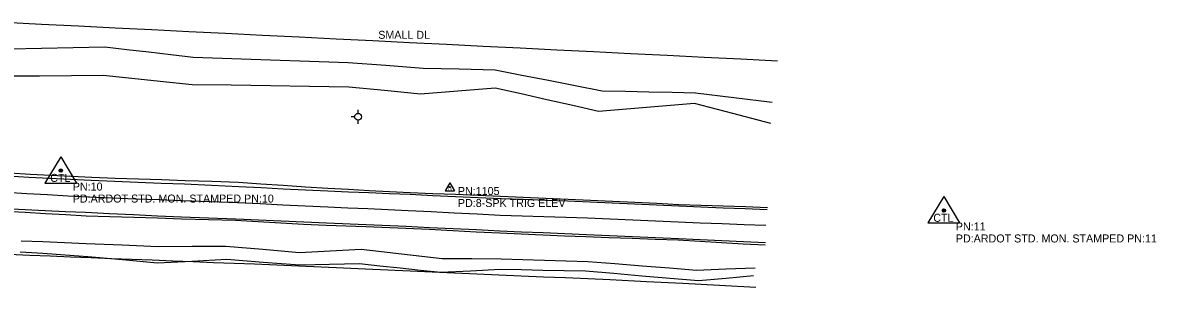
# Model space of a CAD drawing. Extents: x 1138803 to 1169983, y 1655906 to 1658226.
# Drawn here: x 1149908 to 1150616, y 1657386 to 1657552 of the extents above; entities that cross this region are included whole.
import ezdxf

# ---------------------------------------------------------------- set-up
doc = ezdxf.new("R2010")
doc.units = 0
for name, color, linetype in [('S_DITCHLINE', 7, 'Continuous'), ('S_EDGE_PAVEMENT', 7, 'Continuous'), ('S_MSC_PT_SYM', 7, 'Continuous'), ('S_PAVEMENT_CROWN', 7, 'Continuous'), ('S_PRIMARY_CTL', 7, 'Continuous'), ('S_PRIMARY_CTL_ANNOT', 7, 'Continuous'), ('S_SECONDARY_CTL', 7, 'Continuous'), ('S_SECONDARY_CTL_ANNOT', 7, 'Continuous'), ('S_SHOULDER', 7, 'Continuous'), ('S_SURVEY_TEXT_ANNOT', 7, 'Continuous'), ('S_TREE', 7, 'Continuous'), ('S_UTILITY_POLE', 7, 'Continuous')]:
    doc.layers.add(name, color=color, linetype=linetype)

msp = doc.modelspace()

# ---------------------------------------------------------------- linework, layer by layer
at = {"layer": 'S_DITCHLINE'}
for points in [[(1150375.87, 1657501.82), (1150351.88, 1657504.76), (1150327.89, 1657507.69), (1150313.29, 1657508), (1150298.7, 1657508.3), (1150284.1, 1657508.61), (1150269.51, 1657508.91), (1150252.82, 1657512.19), (1150236.14, 1657515.47), (1150219.45, 1657518.75), (1150202.76, 1657522.04), (1150180.28, 1657522.57), (1150157.8, 1657523.11), (1150134.34, 1657524.9), (1150110.88, 1657526.7), (1150086.66, 1657527.53), (1150062.44, 1657528.36), (1150038.22, 1657529.19), (1150014.01, 1657530.02), (1150000.22, 1657531.62), (1149986.44, 1657533.23), (1149972.66, 1657534.83), (1149958.88, 1657536.43), (1149939.08, 1657536.02), (1149919.29, 1657535.62), (1149899.49, 1657535.21)], [(1150374.96, 1657488.71), (1150351.16, 1657494.98), (1150327.36, 1657501.26), (1150312.35, 1657499.99), (1150297.35, 1657498.72), (1150282.34, 1657497.45), (1150267.34, 1657496.18), (1150251.21, 1657499.84), (1150235.08, 1657503.51), (1150218.95, 1657507.18), (1150202.83, 1657510.85), (1150179.42, 1657508.91), (1150156, 1657506.97), (1150133.64, 1657509.21), (1150111.27, 1657511.44), (1150086.79, 1657511.82), (1150062.31, 1657512.2), (1150037.83, 1657512.58), (1150013.35, 1657512.95), (1149999.47, 1657514.36), (1149985.6, 1657515.78), (1149971.72, 1657517.19), (1149957.85, 1657518.6), (1149937.99, 1657518.48), (1149918.12, 1657518.35), (1149898.26, 1657518.23)], [(1150365.15, 1657398.18), (1150346.88, 1657397.42), (1150328.61, 1657396.66), (1150311.6, 1657398.03), (1150294.58, 1657399.39), (1150277.57, 1657400.76), (1150260.55, 1657402.12), (1150247.03, 1657402.53), (1150233.51, 1657402.94), (1150219.99, 1657403.34), (1150206.47, 1657403.75), (1150188.08, 1657403.84), (1150169.7, 1657403.92), (1150157.01, 1657405.37), (1150144.32, 1657406.81), (1150131.63, 1657408.25), (1150118.94, 1657409.69), (1150099.7, 1657408.71), (1150080.46, 1657407.73), (1150057.51, 1657409.72), (1150034.55, 1657411.7), (1150013.35, 1657411.6), (1149992.14, 1657411.5), (1149969.72, 1657412.46), (1149947.31, 1657413.42), (1149933.77, 1657413.98), (1149920.24, 1657414.54), (1149906.71, 1657415.09)], [(1150364.23, 1657393.32), (1150346.97, 1657391.72), (1150329.7, 1657390.13), (1150312.09, 1657391.65), (1150294.47, 1657393.17), (1150276.85, 1657394.7), (1150259.23, 1657396.22), (1150245.9, 1657396.46), (1150232.56, 1657396.71), (1150219.22, 1657396.95), (1150205.88, 1657397.19), (1150187.34, 1657396.24), (1150168.79, 1657395.29), (1150156.09, 1657396.67), (1150143.39, 1657398.05), (1150130.68, 1657399.43), (1150117.98, 1657400.81), (1150099.31, 1657400.39), (1150080.63, 1657399.97), (1150057.86, 1657401.69), (1150035.09, 1657403.41), (1150013.34, 1657402.32), (1149991.6, 1657401.23), (1149969.93, 1657403.2), (1149948.27, 1657405.16), (1149934.18, 1657406.17), (1149920.09, 1657407.18), (1149906, 1657408.18)]]:
    msp.add_lwpolyline(points, dxfattribs=at)
at = {"layer": 'S_EDGE_PAVEMENT'}
for points in [[(1150372.61, 1657434.65), (1150358.85, 1657435.18), (1150345.08, 1657435.72), (1150331.32, 1657436.26), (1150317.56, 1657436.8), (1150303.62, 1657437.45), (1150289.69, 1657438.11), (1150275.76, 1657438.76), (1150261.83, 1657439.41), (1150247.97, 1657439.94), (1150234.12, 1657440.46), (1150220.27, 1657440.99), (1150206.42, 1657441.51), (1150192.21, 1657442.16), (1150178, 1657442.81), (1150163.79, 1657443.46), (1150149.58, 1657444.11), (1150136.74, 1657444.64), (1150123.9, 1657445.18), (1150111.06, 1657445.71), (1150098.22, 1657446.25), (1150084.31, 1657446.94), (1150070.39, 1657447.63), (1150056.48, 1657448.32), (1150042.56, 1657449.01), (1150025.58, 1657449.81), (1150008.59, 1657450.61), (1149994.02, 1657451.17), (1149979.45, 1657451.73), (1149964.88, 1657452.29), (1149950.3, 1657452.86), (1149937.35, 1657453.54), (1149924.4, 1657454.22), (1149911.44, 1657454.9), (1149898.49, 1657455.58)], [(1150371.59, 1657413.89), (1150357.99, 1657414.55), (1150344.39, 1657415.21), (1150330.79, 1657415.87), (1150317.19, 1657416.53), (1150302.85, 1657417.13), (1150288.51, 1657417.74), (1150274.17, 1657418.34), (1150259.83, 1657418.95), (1150246.3, 1657419.54), (1150232.76, 1657420.13), (1150219.22, 1657420.72), (1150205.69, 1657421.31), (1150191.05, 1657422.01), (1150176.42, 1657422.7), (1150161.78, 1657423.4), (1150147.15, 1657424.09), (1150122.21, 1657425.14), (1150097.27, 1657426.19), (1150083.15, 1657426.84), (1150069.03, 1657427.49), (1150054.91, 1657428.15), (1150040.79, 1657428.8), (1150023.75, 1657429.4), (1150006.71, 1657429.99), (1149991.76, 1657430.7), (1149976.81, 1657431.42), (1149961.86, 1657432.13), (1149946.91, 1657432.84), (1149934.28, 1657433.44), (1149921.65, 1657434.05), (1149909.02, 1657434.65), (1149896.39, 1657435.26)]]:
    msp.add_lwpolyline(points, dxfattribs=at)
at = {"layer": 'S_MSC_PT_SYM'}
msp.add_lwpolyline([(1150129.7, 1657546.66), (1150129.7, 1657546.71), (1150129.7, 1657546.66), (1150129.65, 1657546.66), (1150129.7, 1657546.66), (1150129.7, 1657546.61), (1150129.7, 1657546.66), (1150129.75, 1657546.66)], dxfattribs=at)
at = {"layer": 'S_PAVEMENT_CROWN'}
msp.add_lwpolyline([(1150371.93, 1657424.75), (1150358.22, 1657425.27), (1150344.5, 1657425.78), (1150330.79, 1657426.3), (1150317.08, 1657426.82), (1150302.92, 1657427.47), (1150288.77, 1657428.12), (1150274.61, 1657428.77), (1150260.45, 1657429.42), (1150246.82, 1657429.85), (1150233.19, 1657430.27), (1150219.56, 1657430.7), (1150205.93, 1657431.12), (1150191.55, 1657431.84), (1150177.16, 1657432.56), (1150162.78, 1657433.28), (1150148.4, 1657434), (1150135.84, 1657434.57), (1150123.27, 1657435.13), (1150110.71, 1657435.7), (1150098.15, 1657436.27), (1150084.08, 1657436.94), (1150070, 1657437.61), (1150055.93, 1657438.28), (1150041.86, 1657438.95), (1150024.64, 1657439.61), (1150007.43, 1657440.26), (1149992.74, 1657440.82), (1149978.06, 1657441.37), (1149963.37, 1657441.92), (1149948.68, 1657442.47), (1149935.85, 1657443.2), (1149923.02, 1657443.93), (1149910.19, 1657444.66), (1149897.36, 1657445.39)], dxfattribs=at)
at = {"layer": 'S_PRIMARY_CTL'}
for p, q in [((1149931.37, 1657467.86), (1149921.34, 1657451.35)), ((1149931.37, 1657467.86), (1149941.19, 1657451.35)), ((1149921.34, 1657451.35), (1149941.19, 1657451.35)), ((1150483.05, 1657442.88), (1150473.02, 1657426.37)), ((1150483.05, 1657442.88), (1150492.88, 1657426.37)), ((1150473.02, 1657426.37), (1150492.88, 1657426.37))]:
    msp.add_line(p, q, dxfattribs=at)
for centre, radius in [((1149931.37, 1657459.16), 1.04), ((1149931.37, 1657459.16), 0.609), ((1149931.37, 1657459.16), 0.344), ((1150483.05, 1657434.18), 1.04), ((1150483.05, 1657434.18), 0.609), ((1150483.05, 1657434.18), 0.344)]:
    msp.add_circle(centre, radius, dxfattribs=at)
at = {"layer": 'S_SECONDARY_CTL'}
for p, q in [((1150174.47, 1657451.5), (1150171.46, 1657446.55)), ((1150174.47, 1657451.5), (1150177.42, 1657446.55)), ((1150171.46, 1657446.55), (1150177.42, 1657446.55))]:
    msp.add_line(p, q, dxfattribs=at)
for radius in [0.311, 0.183, 0.103]:
    msp.add_circle((1150174.47, 1657448.89), radius, dxfattribs=at)
at = {"layer": 'S_SHOULDER'}
for points in [[(1150372.89, 1657435.91), (1150359.06, 1657436.39), (1150345.22, 1657436.87), (1150331.38, 1657437.34), (1150317.55, 1657437.82), (1150303.73, 1657438.47), (1150289.92, 1657439.13), (1150276.11, 1657439.78), (1150262.29, 1657440.44), (1150248.26, 1657441.09), (1150234.23, 1657441.74), (1150220.19, 1657442.4), (1150206.16, 1657443.05), (1150192.03, 1657443.61), (1150177.9, 1657444.16), (1150163.77, 1657444.72), (1150149.64, 1657445.28), (1150136.79, 1657445.93), (1150123.94, 1657446.59), (1150111.09, 1657447.25), (1150098.24, 1657447.91), (1150084.3, 1657448.85), (1150070.35, 1657449.78), (1150056.41, 1657450.72), (1150042.47, 1657451.66), (1150025.77, 1657452.25), (1150009.07, 1657452.85), (1149994.49, 1657453.32), (1149979.91, 1657453.8), (1149965.33, 1657454.27), (1149950.75, 1657454.75), (1149937.93, 1657455.43), (1149925.11, 1657456.12), (1149912.29, 1657456.81), (1149899.47, 1657457.49)], [(1150371.33, 1657412.38), (1150357.77, 1657413.18), (1150344.22, 1657413.99), (1150330.66, 1657414.79), (1150317.1, 1657415.6), (1150302.69, 1657416.11), (1150288.27, 1657416.62), (1150273.85, 1657417.13), (1150259.43, 1657417.64), (1150245.99, 1657418.21), (1150232.54, 1657418.79), (1150219.09, 1657419.36), (1150205.65, 1657419.93), (1150190.95, 1657420.71), (1150176.26, 1657421.48), (1150161.57, 1657422.25), (1150146.87, 1657423.02), (1150122.01, 1657423.87), (1150097.14, 1657424.73), (1150082.98, 1657425.51), (1150068.82, 1657426.3), (1150054.66, 1657427.09), (1150040.5, 1657427.88), (1150023.61, 1657428.36), (1150006.73, 1657428.85), (1149991.83, 1657429.31), (1149976.94, 1657429.76), (1149962.04, 1657430.22), (1149947.14, 1657430.68), (1149934.45, 1657431.4), (1149921.76, 1657432.12), (1149909.07, 1657432.84), (1149896.37, 1657433.56)]]:
    msp.add_lwpolyline(points, dxfattribs=at)
at = {"layer": 'S_TREE'}
for points in [[(1150379.23, 1657527.75), (1150356.23, 1657528.9), (1150333.24, 1657530.04), (1150310.25, 1657531.19), (1150287.25, 1657532.33), (1150264.26, 1657533.48), (1150241.27, 1657534.62), (1150218.27, 1657535.77), (1150195.28, 1657536.91), (1150172.29, 1657538.06), (1150149.29, 1657539.2), (1150126.3, 1657540.35), (1150103.31, 1657541.49), (1150080.31, 1657542.64), (1150057.32, 1657543.78), (1150034.33, 1657544.92), (1150011.33, 1657546.07), (1149988.34, 1657547.21), (1149965.35, 1657548.36), (1149942.35, 1657549.5), (1149919.36, 1657550.65), (1149896.37, 1657551.79)], [(1150365.62, 1657386.06), (1150342.84, 1657387.23), (1150320.07, 1657388.39), (1150297.29, 1657389.56), (1150274.51, 1657390.72), (1150260.63, 1657391.33), (1150246.74, 1657391.94), (1150232.86, 1657392.55), (1150218.97, 1657393.16), (1150205.09, 1657393.77), (1150191.2, 1657394.39), (1150177.32, 1657395), (1150163.43, 1657395.61), (1150149.55, 1657396.22), (1150135.66, 1657396.83), (1150121.78, 1657397.44), (1150107.89, 1657398.05), (1150094.01, 1657398.66), (1150080.12, 1657399.27), (1150066.24, 1657399.88), (1150052.35, 1657400.49), (1150039.59, 1657401), (1150026.83, 1657401.5), (1150014.06, 1657402), (1150001.3, 1657402.51), (1149988.54, 1657403.01), (1149975.78, 1657403.52), (1149963.02, 1657404.02), (1149950.25, 1657404.52), (1149937.49, 1657405.03), (1149924.73, 1657405.53), (1149911.97, 1657406.04), (1149899.21, 1657406.54)]]:
    msp.add_lwpolyline(points, dxfattribs=at)
at = {"layer": 'S_UTILITY_POLE'}
for p, q in [((1150117.1, 1657494.98), (1150117.1, 1657497.22)), ((1150115, 1657492.84), (1150112.68, 1657492.84)), ((1150117.17, 1657488.43), (1150117.17, 1657490.75))]:
    msp.add_line(p, q, dxfattribs=at)
msp.add_circle((1150117.1, 1657492.87), 2.13, dxfattribs=at)

# ---------------------------------------------------------------- texts
at = {"layer": 'S_PRIMARY_CTL'}
for p in [(1149924.78, 1657452.09), (1150476.47, 1657427.1)]:
    msp.add_text('CTL', height=5, rotation=360, dxfattribs=at).set_placement(p)
at = {"layer": 'S_PRIMARY_CTL_ANNOT'}
for s, p in [('PN:10', (1149938.87, 1657446.66)), ('PD:ARDOT STD. MON. STAMPED PN:10', (1149938.87, 1657439.16)), ('PN:11', (1150490.55, 1657421.68)), ('PD:ARDOT STD. MON. STAMPED PN:11', (1150490.55, 1657414.18))]:
    msp.add_text(s, height=5, dxfattribs=at).set_placement(p)
at = {"layer": 'S_SECONDARY_CTL'}
msp.add_text('TV', height=1.5, rotation=360, dxfattribs=at).set_placement((1150173.26, 1657446.88))
at = {"layer": 'S_SECONDARY_CTL_ANNOT'}
for s, p in [('PN:1105', (1150179.47, 1657443.89)), ('PD:8-SPK TRIG ELEV', (1150179.47, 1657436.39))]:
    msp.add_text(s, height=5, dxfattribs=at).set_placement(p)
at = {"layer": 'S_SURVEY_TEXT_ANNOT'}
msp.add_text('SMALL DL', height=5, dxfattribs=at).set_placement((1150129.7, 1657541.66))

doc.saveas('drawing.dxf')
